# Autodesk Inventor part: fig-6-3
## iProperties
Created: 2004-05
Part Number: fig-6-3
Document SubType Name: Modeling
Designer: CADCIM Technologies
Manufacturer: Standard
Standards Organization: Custom
Author: CADCIM Technologies
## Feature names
1. Extrusion1
2. Hole1
3. Circular Pattern1
